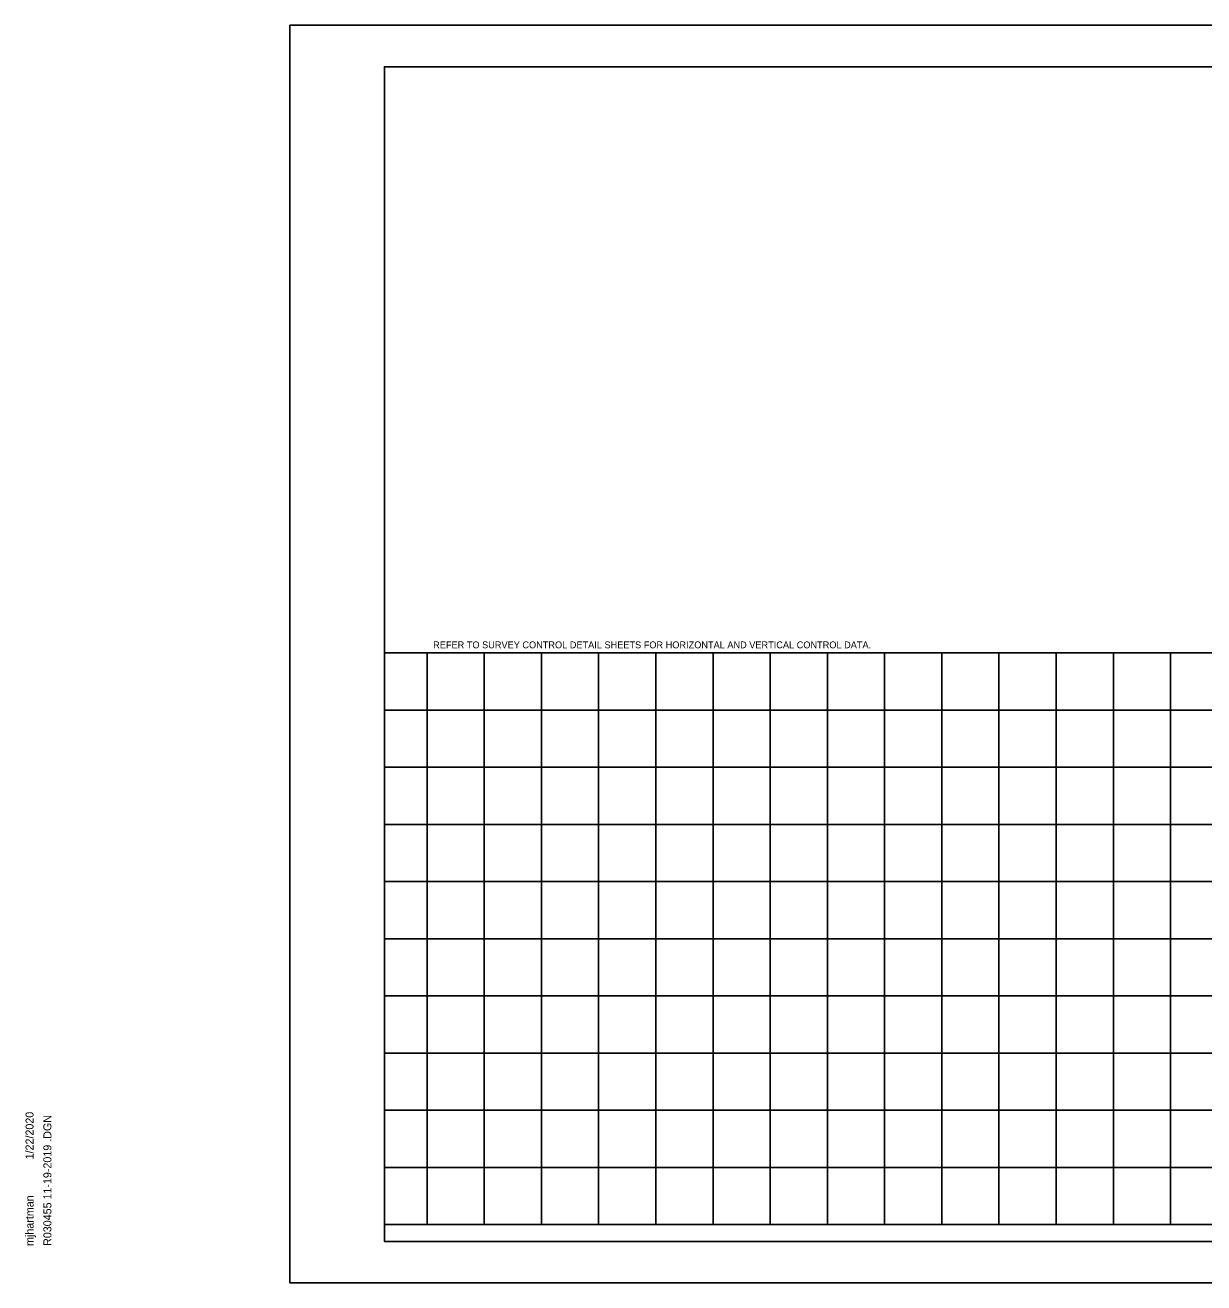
# Model space of a CAD drawing. Extents: x 1369502 to 1371590, y 379102 to 380202.
# Drawn here: x 1369502 to 1370533, y 379102 to 380202 of the extents above; entities that cross this region are included whole.
import ezdxf

# ---------------------------------------------------------------- set-up
doc = ezdxf.new("R2010")
doc.units = 0
for name, color, linetype in [('Level 63', 7, 'Continuous'), ('R_Border', 7, 'Continuous'), ('R_Border Notes', 7, 'Continuous'), ('R_Grid', 7, 'Continuous'), ('R_No Plot', 7, 'Continuous'), ('R_Survey Control', 7, 'Continuous')]:
    doc.layers.add(name, color=color, linetype=linetype)

msp = doc.modelspace()

# ---------------------------------------------------------------- linework, layer by layer
at = {"layer": 'Level 63'}
msp.add_lwpolyline([(1369733.7, 380202.4), (1371433.7, 380202.4), (1371433.7, 379102.4), (1369733.7, 379102.4)], close=True, dxfattribs=at)
at = {"layer": 'R_Border'}
for p, q in [((1369816.4, 380166), (1371397.3, 380166)), ((1369816.4, 379138.7), (1369816.4, 380166)), ((1369816.4, 379138.7), (1369816.4, 379138.7)), ((1371397.3, 379138.7), (1369816.4, 379138.7))]:
    msp.add_line(p, q, dxfattribs=at)
at = {"layer": 'R_Border Notes'}
msp.add_line((1371397.3, 379653.4), (1369816.4, 379653.4), dxfattribs=at)
at = {"layer": 'R_Grid'}
for p, q in [((1369853.7, 379153.4), (1369853.7, 379653.4)), ((1369903.7, 379153.4), (1369903.7, 379653.4)), ((1369953.7, 379153.4), (1369953.7, 379653.4)), ((1370003.7, 379153.4), (1370003.7, 379653.4)), ((1370053.7, 379153.4), (1370053.7, 379653.4)), ((1370103.7, 379153.4), (1370103.7, 379653.4)), ((1370153.7, 379153.4), (1370153.7, 379653.4)), ((1370203.7, 379153.4), (1370203.7, 379653.4)), ((1370253.7, 379153.4), (1370253.7, 379653.4)), ((1370303.7, 379153.4), (1370303.7, 379653.4)), ((1370353.7, 379153.4), (1370353.7, 379653.4)), ((1370403.7, 379153.4), (1370403.7, 379653.4)), ((1370453.7, 379153.4), (1370453.7, 379653.4)), ((1370503.7, 379153.4), (1370503.7, 379653.4)), ((1371397.3, 379603.4), (1369816.4, 379603.4)), ((1371397.3, 379553.4), (1369816.4, 379553.4)), ((1371397.3, 379503.4), (1369816.4, 379503.4)), ((1371397.3, 379453.4), (1369816.4, 379453.4)), ((1371397.3, 379403.4), (1369816.4, 379403.4)), ((1371397.3, 379353.4), (1369816.4, 379353.4)), ((1371397.3, 379303.4), (1369816.4, 379303.4)), ((1371397.3, 379253.4), (1369816.4, 379253.4)), ((1371397.3, 379203.4), (1369816.4, 379203.4)), ((1371397.3, 379153.4), (1369816.4, 379153.4))]:
    msp.add_line(p, q, dxfattribs=at)
at = {"layer": 'R_No Plot'}
for points in [[(1370986, 380166), (1370986, 380116.6), (1371164.7, 380116.6), (1371164.7, 380102), (1371275.9, 380102.4), (1371275.9, 379984), (1371397.3, 379983.7), (1371397.3, 379653.4), (1369816.4, 379653.4), (1369816.4, 380166)], [(1371397.3, 379653.4), (1371397.3, 379138.7), (1369816.4, 379138.7), (1369816.4, 379653.4)]]:
    msp.add_lwpolyline(points, close=True, dxfattribs=at)

# ---------------------------------------------------------------- texts
at = {"layer": 'R_Border'}
for s, p in [('1/22/2020', (1369509.6, 379210.4)), ('R030455 11-19-2019 .DGN', (1369525.2, 379134.7)), ('mjhartman', (1369509.6, 379134.7))]:
    msp.add_text(s, height=7, rotation=90, dxfattribs=at).set_placement(p)
at = {"layer": 'R_Survey Control'}
msp.add_text('REFER TO SURVEY CONTROL DETAIL SHEETS FOR HORIZONTAL AND VERTICAL CONTROL DATA.', height=6, rotation=360, dxfattribs=at).set_placement((1369859, 379657.4))

doc.saveas('drawing.dxf')
